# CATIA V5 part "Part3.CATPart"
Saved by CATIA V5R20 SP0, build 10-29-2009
Part number: Part3
Bounding box of the stored display mesh (mm): x 0 to 6, y -4 to 4, z -3.991 to 60.991
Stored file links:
  E:\Ehsan\Catia\Tamrin\Digital Mockup\4\Part3.CATPart
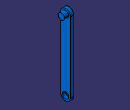
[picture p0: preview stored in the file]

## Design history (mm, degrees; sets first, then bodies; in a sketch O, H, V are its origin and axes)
Body1 (main body)
  Sketch1 on yz-plane, origin (0, 0, 0), H (0, 1, 0), V (0, 0, 1)
    construction line L1 (0, 0) -> (0, 57)
    line L2 (-4, 0) -> (-4, 57)
    line L3 (4, 57) -> (4, 0)
    arc A1 centre (0, 57) radius 4 from (-4, 57) to (4, 57) cw
    arc A2 centre (0, 0) radius 4 from (4, 0) to (-4, 0) cw
    length L1 = 57
    distance L1 L2 = 4
    vertical: L1 V
    tangency: A1 L2, A2 L2, A1 L3, A2 L3
  Pad1: profile Sketch1, direction (1, 0, 0), length 2.5
  Sketch2 on end face of Pad1, origin (2.5, 0, 0), H (0, 1, 0), V (0, 0, 1)
    circle A1 centre (0, 0) radius 2.5
    radius A1 = 2.5
  Pocket1: profile Sketch2, direction (-1, 0, 0), through (limit type 3)
  Sketch3 on end face of Pad1, origin (2.5, 0, 0), H (0, 1, 0), V (0, 0, 1)
    circle A1 centre (0, 57) radius 2.5
    reference projected arc E1 centre (0, 57) radius 4 from (4, 57) to (-4, 57) ccw from edge [face of Pad1 from Sketch1.A1 | end face of Pad1]
    radius A1 = 2.5
    concentricity: A1 E1
  Pad2: profile Sketch3, direction (1, 0, 0), length 3.5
